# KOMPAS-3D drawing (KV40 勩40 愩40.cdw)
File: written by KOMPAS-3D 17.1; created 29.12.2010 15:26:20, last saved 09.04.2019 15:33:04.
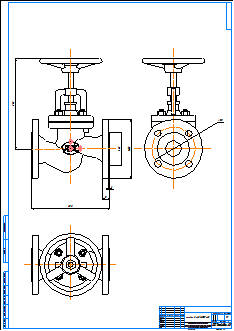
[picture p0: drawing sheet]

Title block, sheet 1: name: гранвэл Ду40 МФ Ру25; material: Внимание! Данный продукт является объектом авторского права ООО «Торговый Дом АДЛ». / Запрещается изменение, копирование, распространение / (в том числе путем копирования на другие сайты и ресурсы в Интернете) / или любое иное использование информации и объектов без предварительного / согласия правообладателя (ООО «Торговый Дом АДЛ»).; scale: 1:1; sheets: 1; organisation: ООО "Торговый дом АДЛ"; sheet format: A1; stored path: \\adlc.lan\data\АДЛ_ПКД\3D-модели\ADL production\Вентили ГРАНВЕНТ\KV40\KOMPAS 2D\KV 40 Ду40.cdw

Views: Спереди 1, Проекционный вид 2, Проекционный вид 3
Dimensions and other numbers on the sheet: 88; 150; 200; 3; 18; 110; 230; 1:1; 1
